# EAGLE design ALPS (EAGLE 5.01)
MFG: AVX; PN: TCJR106M006R0500
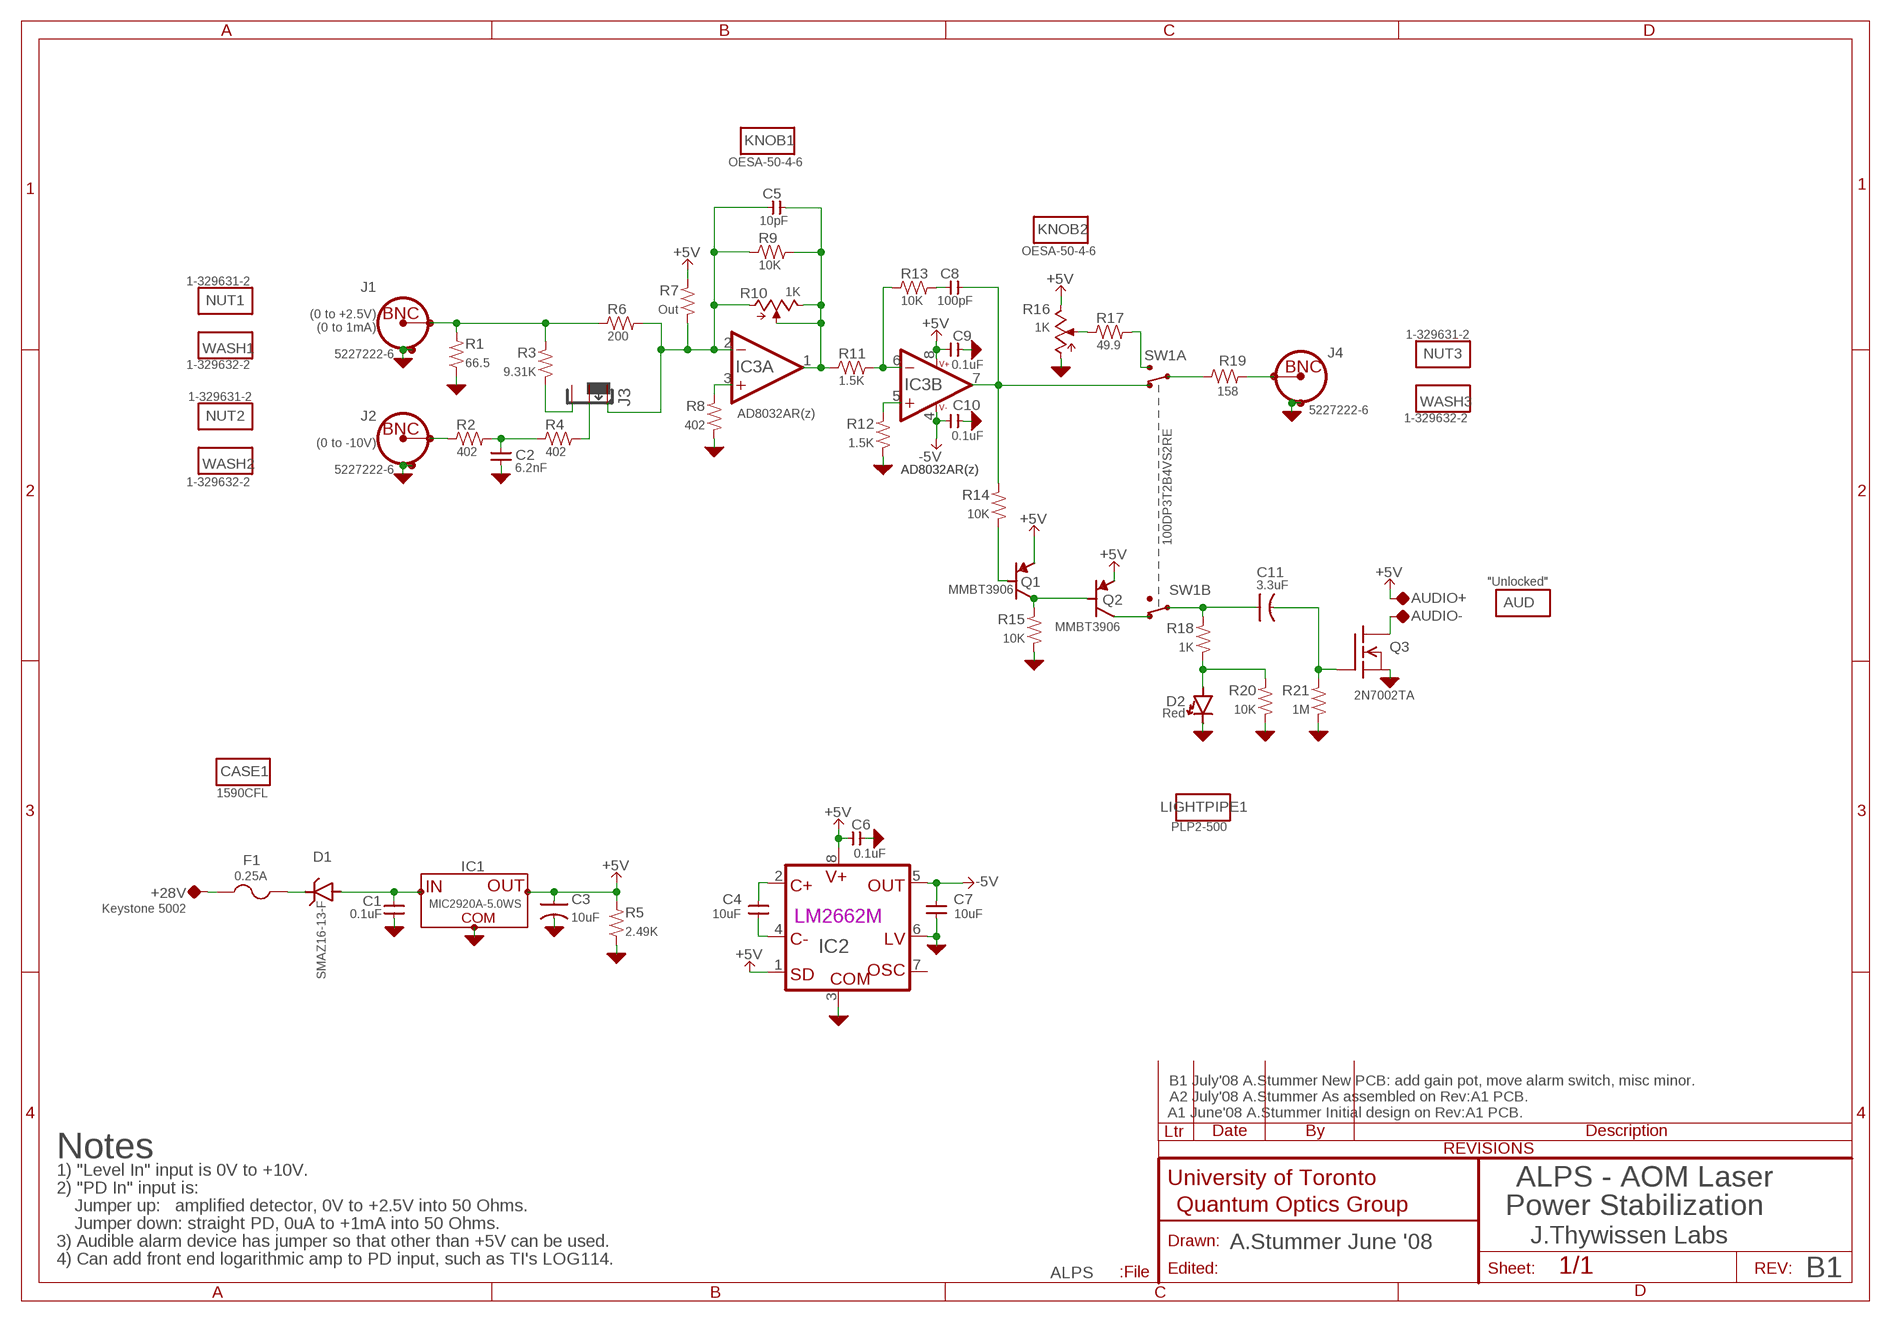
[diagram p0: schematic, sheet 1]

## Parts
+28V  Keystone 5002  TP-0.042B  [TP-0.042B]
AUD  "Unlocked"  MISC  [MISC]
AUDIO+  Keystone 5002  TP-0.042B  [TP-0.042B]
AUDIO-  Keystone 5002  TP-0.042B  [TP-0.042B]
C1  0.1uF  CAP-V-0805  [2012(0805)]
C2  6.2nF  CAP-V-0805  [2012(0805)]
C3  10uF  CAP-POL-1206  [3216(1206)]
C4  10uF  CAP-V-0805  [2012(0805)]
C5  10pF  CAP-H-0805  [2012(0805)]
C6  0.1uF  CAP-H-0805  [2012(0805)]
C7  10uF  CAP-V-0805  [2012(0805)]
C8  100pF  CAP-H-0805  [2012(0805)]
C9  0.1uF  CAP-H-0805  [2012(0805)]
C10  0.1uF  CAP-H-0805  [2012(0805)]
C11  3.3uF  CAP-POL-0805  [2012(0805)]
CASE1  1590CFL  MISC  [MISC]
D1  SMAZ16-13-F  ZENER-EIA-A  [EIA-A(SMA)]
D2  Red  LED-1209  [1209]
F1  0.25A  FUSE-5X20-4  [FUSE]
IC1  MIC2920A-5.0WS  78-SOT223  [SOT223]
IC2  LM2662M  LM2663M  [SOIC-8]
IC3  AD8032AR(z)  OPAMP_DUAL-SOIC8  [SOIC-8]
J1  5227222-6  CONN-BNC-TYPE1VERT  [CONN-BNC-AMP-TYPE1VERT]
J2  5227222-6  CONN-BNC-TYPE1VERT  [CONN-BNC-AMP-TYPE1VERT]
J3  JUMPER-1X3-3  [JUMPER-3]
J4  5227222-6  CONN-BNC-TYPE1VERT  [CONN-BNC-AMP-TYPE1VERT]
KNOB1  OESA-50-4-6  MISC  [MISC]
KNOB2  OESA-50-4-6  MISC  [MISC]
LIGHTPIPE1  PLP2-500  MISC  [MISC]
NUT1  1-329631-2  MISC  [MISC]
NUT2  1-329631-2  MISC  [MISC]
NUT3  1-329631-2  MISC  [MISC]
Q1  MMBT3906  BJT-PNP-SOT23  [SOT23]
Q2  MMBT3906  BJT-PNP-SOT23  [SOT23]
Q3  2N7002TA  MOSFET-N-SOT23  [SOT23]
R1  66.5  R-V-0805  [2012(0805)]
R2  402  R-H-0805  [2012(0805)]
R3  9.31K  R-V-0805  [2012(0805)]
R4  402  R-H-0805  [2012(0805)]
R5  2.49K  R-V-0805  [2012(0805)]
R6  200  R-H-0805  [2012(0805)]
R7  Out  R-V-0805  [2012(0805)]
R8  402  R-V-0805  [2012(0805)]
R9  10K  R-H-0805  [2012(0805)]
R10  1K  POT-PRECISION_SPR_RV8  [PRECISION-SPR-RV8(POT)]
R11  1.5K  R-H-0805  [2012(0805)]
R12  1.5K  R-V-0805  [2012(0805)]
R13  10K  R-H-0805  [2012(0805)]
R14  10K  R-V-0805  [2012(0805)]
R15  10K  R-V-0805  [2012(0805)]
R16  1K  POT-PRECISION_SPR_RV8  [PRECISION-SPR-RV8(POT)]
R17  49.9  R-H-0805  [2012(0805)]
R18  1K  R-V-0805  [2012(0805)]
R19  158  R-H-0805  [2012(0805)]
R20  10K  R-V-0805  [2012(0805)]
R21  1M  R-V-0805  [2012(0805)]
SW1  100DP3T2B4VS2RE  SWITCH_DPDT-ESWITCH_100DP?VS2  [SWITCH-ESWITCH_100DP?VS2]
WASH1  1-329632-2  MISC  [MISC]
WASH2  1-329632-2  MISC  [MISC]
WASH3  1-329632-2  MISC  [MISC]

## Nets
+5V: AUDIO+.TP C3.2(POS) C6.1 C9.1 IC1.3(OUT) IC2.1(SD) IC2.8(V+) IC3.8(.:V+) Q1.2(E) Q2.2(E) R5.2 R7.2 R16.CW
-5V: C7.2 C10.1 IC2.5(OUT) IC3.4(.:V-)
AGND: C1.1 C2.1 C3.1(NEG) C6.2 C7.1 C9.2 C10.2 D2.K(C) IC1.2@1(COM) IC2.3(COM) IC2.6(LV) J1.SHIELD1 J1.SHIELD2 J2.SHIELD1 J2.SHIELD2 J4.SHIELD1 J4.SHIELD2 Q3.2(S) R1.1 R5.1 R8.1 R12.1 R15.1 R16.CCW R20.1 R21.1
N$1: J4.CONDUCTOR R19.2
N$2: C8.2 IC3.7(B:OUT) R14.2 SW1.NC1(A:NC1)
N$3: IC3.6(B:-IN) R11.2 R13.1
N$4: C8.1 R13.2
N$5: R19.1 SW1.C1(A:COM1)
N$6: R17.2 SW1.NO1(A:NO1)
N$7: J2.CONDUCTOR R2.1
N$8: IC3.5(B:+IN) R12.2
N$9: Q1.3(C) Q2.1(B) R15.2
N$10: J1.CONDUCTOR R1.2 R3.2 R6.1
N$11: Q1.1(B) R14.1
N$12: C11.2(POS) R18.2 SW1.C2(B:COM1)
N$13: D2.A R18.1 R20.2
N$14: Q2.3(C) SW1.NC2(B:NC1)
N$15: C11.1(NEG) Q3.1(G) R21.2
N$16: AUDIO-.TP Q3.3(D)
N$17: C1.2 D1.1A(A) IC1.1(VI)
N$18: C4.2 IC2.2(C+)
N$19: +28V.TP F1.1A
N$20: D1.2K(C) F1.2A
N$21: C5.2 IC3.1(A:OUT) R9.2 R10.CW R10.W R11.1
N$22: C5.1 IC3.2(A:-IN) J3.1 R6.2 R7.1 R9.1 R10.CCW
N$23: J3.2 R4.2
N$24: R16.W R17.1
N$25: IC3.3(A:+IN) R8.2
N$26: C4.1 IC2.4(C-)
N$27: C2.2 R2.2 R4.1
N$29: J3.3 R3.1
Unconnected: IC2.7(OSC) SW1.NO2(B:NO1)

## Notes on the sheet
- (0 to +2.5V)
- (0 to 1mA)
- (0 to -10V)
- B1 July'08 A.Stummer New PCB: add gain pot, move alarm switch, misc minor.
- A2 July'08 A.Stummer As assembled on Rev:A1 PCB.
- A1 June'08 A.Stummer Initial design on Rev:A1 PCB.
- Notes
- 1) "Level In" input is 0V to +10V.
- ALPS - AOM Laser
- 2) "PD In" input is:
- Jumper up:   amplified detector, 0V to +2.5V into 50 Ohms. | Power Stabilization
- Jumper down: straight PD, 0uA to +1mA into 50 Ohms.
- 3) Audible alarm device has jumper so that other than +5V can be used. | A.Stummer June '08 | J.Thywissen Labs
- 4) Can add front end logarithmic amp to PD input, such as TI's LOG114.
- B1

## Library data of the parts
+28V AUDIO+ AUDIO- = QuantumOptics:TP: Testpoint, test point on schematic, on PCB either SMT pad, small hole or loop style TP.
AUD CASE1 KNOB1 KNOB2 LIGHTPIPE1 NUT1-NUT3 WASH1-WASH3 = QuantumOptics:MISC: Miscellaneous Part, just a placeholder for miscellaeous parts
C1 C2 C4 C7 = QuantumOptics:CAP-V-: Cap, SMT and Through-hole, 0402 and up.
C3 C11 = QuantumOptics:CAP-POL-: Capacitor, Polarized, SMT 0805 and up, probably tantalum.
C5 C6 C8-C10 = QuantumOptics:CAP-H-: Cap, SMT and Through-hole, 0402 and up.
D1 = QuantumOptics:ZENER: Zener
D2 = QuantumOptics:LED: LED
F1 = QuantumOptics:FUSE: Fuse
IC1 = QuantumOptics:78*: Positive regulator, probably fixed output. E.g. SOT-223 Micrel MIC2920, http://www.micrel.com/_PDF/mic2920.pdf e.g. uA78L05ACPK, http://www-s.ti.com/sc/ds/ua78l05a.pdf
IC2 = QuantumOptics:LM2663: LM2663, switched cap DC-DC converter. Inverter, doubler, supply splitter.
IC3 = QuantumOptics:OPAMP_DUAL: Dual Op Amp, common pinouts. Based on http://www.analog.com/static/imported-files/data_sheets/AD8651_8652.pdf
J1 J2 J4 = QuantumOptics:CONN-BNC: BNC PCB, horizontal or vertical, e.g. vertical: Amp 227677-1, nut 1-329631-2, shoulder washer 330620. The two shield connections allow the assembly on either side of the board. Horiz isolated: 5227222-6, http://catalog.tycoelectronics.com/TE/bin/TE.Connect?C=1&M=BYPN&TCPN=5227222-6&RQPN=5227222-6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; DESC: Input?
J3 = QuantumOptics:JUMPER-1X3: Jumper, header, SIP on 0.1" grid, for option selection.
Q1 Q2 = QuantumOptics:BJT-PNP: PNP BJT, generic, p/n defined by VALUE field. E.g. Fairchild MMBT3906 (abs max 40V, 200mA. hFE>80@10mA.
Q3 = QuantumOptics:MOSFET-N: Mosfet, N-Channel, generic enhancement mode N-FET.
R1 R3 R5 R7 R8 R12 R14 R15 R18 R20 R21 = QuantumOptics:R-V-*: Resistor, SMT & Through-Hole, vertical symbol
R2 R4 R6 R9 R11 R13 R17 R19 = QuantumOptics:R-H-*: Resistor, SMT & Through-Hole, horizontal symbol
R10 R16 = QuantumOptics:POT: Pot, regular or trimpot
SW1 = QuantumOptics:SWITCH_DPDT: Switch, DPDT

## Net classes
0 default: width 0.203 mm, clearance 0.203 mm

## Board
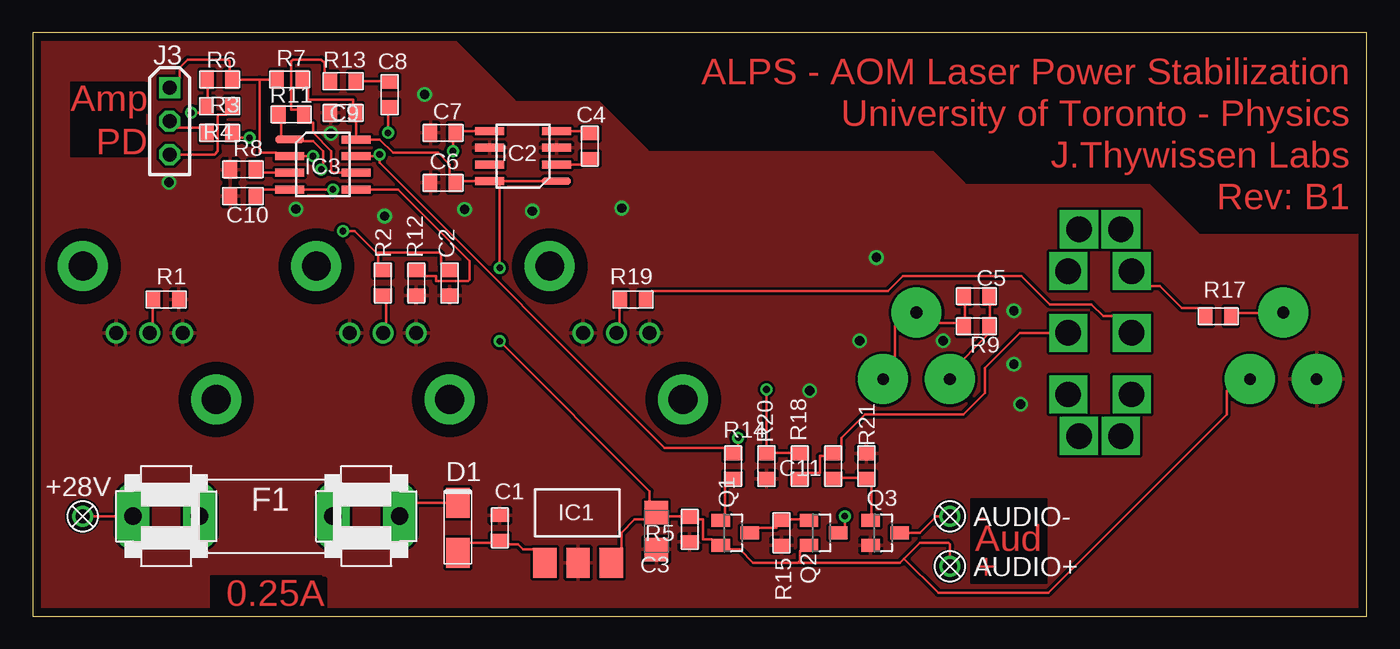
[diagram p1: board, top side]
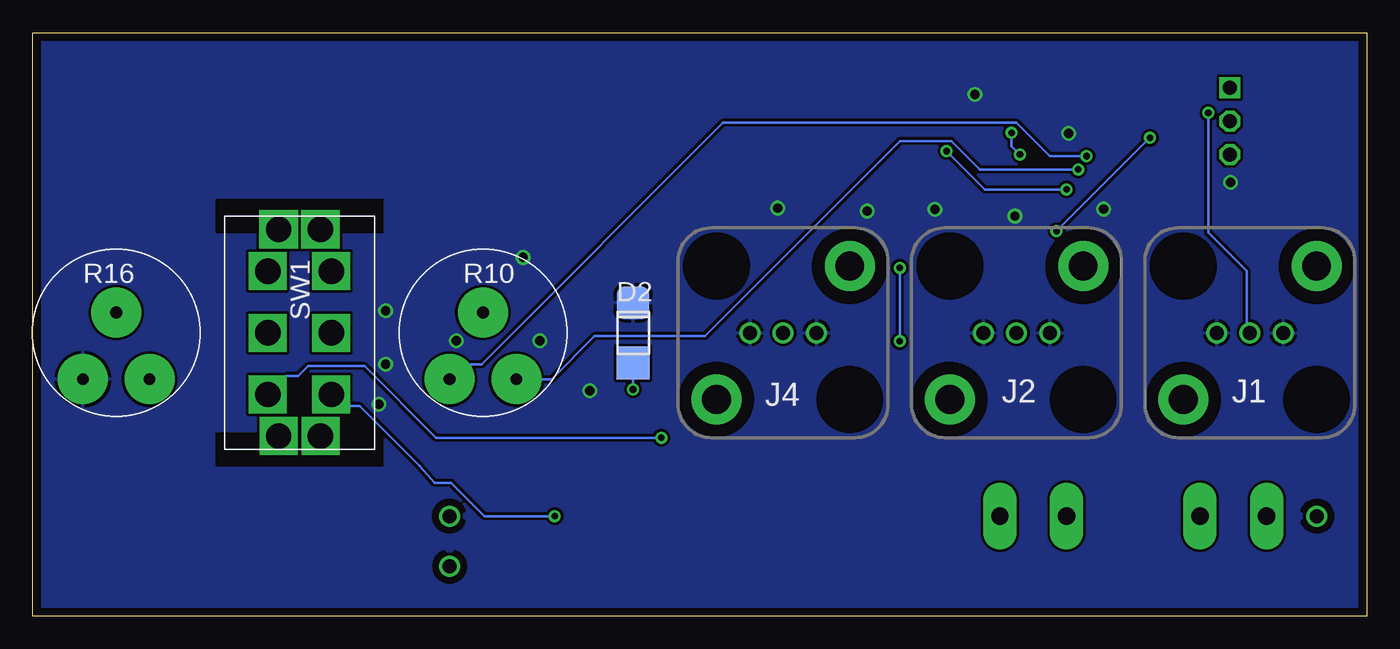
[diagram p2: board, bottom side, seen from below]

Size 101.6 x 44.45 mm. Coordinates in mm from the lower left corner, seen from the top.
Outline: 0,0 101.6,0 101.6,44.45 0,44.45 0,0
Copper layers (1*16): Top 0.035mm / dielectric 1.5mm / Bottom 0.035mm
Design rules "DRC standard check (8mil trace and gap, 20mil drill, etc)": minimum track width 7mil, minimum drill 20mil, track to track 7mil, track to pad 7mil, pad to pad 7mil, via to via 7mil, smd to smd 7mil, copper to edge 25mil, drill to drill 8mil, minimum pad ring 10mil, minimum via ring 8mil, stop-mask expansion 4mil, vias tented up to drill 0mil, thermal gap 10mil
tRestrict: 19 lines

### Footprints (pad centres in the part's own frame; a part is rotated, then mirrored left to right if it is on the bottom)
TP-0.042B = drill 1.067 round: TP 0,0
2012(0805) = smd 1.016 x 1.397: 1 -0.953,0; 2 0.953,0
3216(1206) = smd 1.8 x 1.8: 1 -1.4,0; 2 1.4,0
EIA-A(SMA) = smd 2.3 x 1.8: 1A -1.905,0; 2K 1.905,0
1209 = smd 2.5 x 2.5: A 2.3,0; K -2.3,0
FUSE = drill 1.321 pad 2.54 long: 1A -10.16,0; 1B -5.08,0; 2A 10.16,0; 2B 5.08,0
SOT223 = smd 1.778 x 2.286: 1 -2.54,-2.54; 2@1 0,-2.54; 3 2.54,-2.54
SOIC-8 = smd 0.6 x 2.2: 1 -1.27,-2.54; 2 0,-2.54; 3 1.27,-2.54; 4 2.54,-2.54; 5 2.54,2.54; 6 1.27,2.54; 7 0,2.54; 8 -1.27,2.54
CONN-BNC-AMP-TYPE1VERT = drill 1.067 round: CONDUCTOR 0,0; SHIELD1 -2.54,0; SHIELD2 2.54,0 | drill 2.184 pad 3.81 round: MTG1 -5.08,-5.08; MTG2 5.08,5.08
JUMPER-3 = drill 1.067 square: 1 0,2.54 | drill 1.067 octagon: 2 0,0; 3 0,-2.54
SOT23 = smd 1 x 1.4: 1 -0.953,-0.953; 2 0.953,-0.953; 3 0,1.27
PRECISION-SPR-RV8(POT) = drill 0.889 pad 3.81 round: CCW -2.54,-3.531; CW 2.54,-3.531; W 0,1.549
SWITCH-ESWITCH_100DP?VS2 = drill 1.93 square: C1 -2.42,0; C2 2.42,0; MTG3 1.595,-7.875; MTG4 -1.595,-7.875; NC1 -2.42,-4.7; NC2 2.42,-4.7; NO1 -2.42,4.7; NO2 2.42,4.7 | drill 1.93 pad 2.946 square: MTG1 -1.595,7.875; MTG2 1.595,7.875

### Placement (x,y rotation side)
+28V  3.81,7.62 180 top
AUD  not placed on the board
AUDIO+  69.85,3.81 270 top
AUDIO-  69.85,7.62 0 top
C1  35.56,6.73 270 top
C2  31.75,25.4 90 top
C3  47.5,6.48 90 top
C4  42.42,35.81 270 top
C5  71.88,24.38 180 top
C6  31.24,33.02 180 top
C7  31.24,36.83 0 top
C8  27.18,39.75 270 top
C9  23.62,38.35 180 top
C10  16,32 180 top
C11  60.96,11.43 90 top
CASE1  not placed on the board
D1  32.38,6.73 90 top
D2  55.88,21.59 270 bottom
F1  17.78,7.62 0 top
IC1  41.53,6.6 0 top
IC2  37.34,34.42 90 top
IC3  22.1,35.05 270 top
J1  8.89,21.59 0 bottom
J2  26.67,21.59 0 bottom
J3  10.41,37.72 0 top
J4  44.45,21.59 0 bottom
KNOB1  not placed on the board
KNOB2  not placed on the board
LIGHTPIPE1  not placed on the board
NUT1  not placed on the board
NUT2  not placed on the board
NUT3  not placed on the board
Q1  53.34,6.35 270 top
Q2  60.07,6.35 270 top
Q3  64.77,6.35 270 top
R1  10.16,24.13 180 top
R2  26.67,25.4 90 top
R3  14.22,38.86 180 top
R4  14.22,36.83 180 top
R5  50.04,6.6 90 top
R6  14.22,40.89 0 top
R7  19.56,40.89 0 top
R8  16,34.04 0 top
R9  71.88,22.1 180 top
R10  67.31,21.59 0 bottom
R11  19.68,38.23 0 top
R12  29.21,25.4 90 top
R13  23.62,40.77 0 top
R14  53.34,11.43 90 top
R15  57.02,6.35 90 top
R16  95.25,21.59 0 bottom
R17  90.3,22.86 180 top
R18  58.42,11.43 270 top
R19  45.72,24.13 180 top
R20  55.88,11.43 90 top
R21  63.5,11.43 270 top
SW1  81.28,21.59 0 bottom
U$18  [TITLEBLOCK_PCB]  not placed on the board
WASH1  not placed on the board
WASH2  not placed on the board
WASH3  not placed on the board

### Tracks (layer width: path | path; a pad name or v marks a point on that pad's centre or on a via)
+5V  (via drill 0.51)
  Top 0.203: IC2.8 32.64,33.15 C6.1 31.75,33.66 31.75,34.42 30.86,35.31 27.43,35.31 26.42,36.32 IC3.8 24.64,37.72 C9.1 24.38,38.99 24.38,39.37 20.95,39.37 20.95,40.26 R7.2 | IC2.8 IC2.1 | C3.2 48.39,7.62 49.4,7.62 R5.2 50.67,7.37 51.05,7.37 51.05,5.84 51.69,5.84 Q1.2 53.09,5.08 53.85,5.08 54.86,4.06 58.29,4.06 58.36,4.13 | 58.36,4.13 58.42,4.19 58.42,4.95 Q2.2 | IC1.3 44.83,5.08 44.83,6.35 45.85,7.37 46.61,7.37 C3.2 | 66.36,4.38 66.04,4.06 58.42,4.06 58.36,4.13 | 66.36,4.38 67.56,5.59 69.72,5.59 69.85,5.46 AUDIO+.TP | R16.CW 90.93,17.14 90.93,15.37 77.34,1.78 68.96,1.78 66.36,4.38 | v35.56,26.54 35.56,32.89 IC2.8 | v35.56,20.95 46.99,9.53 46.99,8.76 C3.2
  Bottom 0.203: v35.56,20.95 v35.56,26.54
-5V  (via drill 0.51)
  Top 0.203: C10.1 17.4,32.51 IC3.4 v22.86,32.51 | IC2.5 32.64,36.96 C7.2 32,36.2 v32,35.43
  Bottom 0.203: v22.86,32.51 29.08,32.51 v32,35.43
AGND  (via drill 0.71)
  other vias: 29.84,39.75 32.89,30.99 26.8,30.48 22.71,36.78 20.04,31.01 10.36,33.05 38.05,30.86 44.86,31.09 69.34,20.98 74.73,23.27 74.73,19.2 75.23,16.15 62.99,20.98 59.18,17.17 64.26,27.33
  pour Top: 0,0 101.6,0 101.6,29.21 88.9,29.21 85.09,33.02 71.12,33.02 68.58,35.56 46.99,35.56 43.18,39.37 36.83,39.37 31.75,44.45 0,44.45
  pour Bottom: 0,0 101.6,0 101.6,44.45 0,44.45
N$1
  Top 0.203: R19.2 44.7,23.5 44.7,22.35 J4.CONDUCTOR
N$2  (via drill 0.51)
  Top 0.203: 26.42,35.05 26.42,34.54 48.13,12.83 52.7,12.83 R14.2 53.72,12.83 v53.72,13.59 | IC3.7 26.42,35.05 | v27.05,36.83 27.05,38.35 C8.2 | 26.42,35.05 v26.42,35.18
  Bottom 0.203: v27.05,36.83 27.05,35.81 v26.42,35.18 | v53.72,13.59 70.87,13.59 76.33,19.05 80.64,19.05 81.41,18.29 82.3,18.29 SW1.NC1
N$3
  Top 0.203: IC3.6 22.86,33.78 22.73,33.91 22.73,35.43 21.34,36.83 21.34,37.59 21.08,37.59 R11.2 20.19,38.61 19.68,38.61 19.68,42.29 19.81,42.42 21.97,42.42 22.23,42.16 22.23,41.4 R13.1
N$4
  Top 0.203: R13.2 26.54,40.77 C8.1
N$5
  Top 0.203: R19.1 47.12,24.77 65.15,24.77 66.29,25.91 75.31,25.91 77.47,23.75 80.64,23.75 81.53,22.86 82.3,22.86 SW1.C1
N$6
  Top 0.203: R17.2 88.9,23.5 87.5,23.5 85.85,25.15 85.09,25.15 SW1.NO1
N$7
  Top 0.203: R2.1 26.92,24 26.92,22.35 J2.CONDUCTOR
N$8
  Top 0.203: R12.2 29.84,25.91 30.73,25.91 30.73,25.53 33.15,25.53 33.27,25.65 33.27,27.05 27.81,32.51 IC3.5
N$9
  Top 0.203: Q2.1 58.42,7.37 57.66,7.37 R15.2 56.64,6.86 56.64,6.73 55.24,6.73 Q1.3
N$10  (via drill 0.51)
  Top 0.203: R6.1 13.34,40.26 13.34,39.5 R3.2 12.83,38.35 v12.06,38.35 | R1.2 9.14,23.5 9.14,22.35 J1.CONDUCTOR
  Bottom 0.203: v12.06,38.35 12.06,29.21 9.14,26.29 9.14,22.35 J1.CONDUCTOR
N$11
  Top 0.203: R14.1 52.7,10.03 52.7,7.75 Q1.1
N$12
  Top 0.203: R18.2 59.05,10.92 59.94,10.92 59.94,12.19 60.33,12.19 C11.2 61.59,12.83 61.59,13.59 63.37,15.37 70.87,15.37 72.52,17.02 72.52,18.92 75.18,21.59 SW1.C2
N$13  (via drill 0.51)
  Top 0.203: R18.1 57.78,12.45 56.52,12.45 R20.2 v55.88,17.27
  Bottom 0.203: v55.88,17.27 D2.A
N$14  (via drill 0.51)
  Top 0.203: v61.85,7.62 61.85,6.73 Q2.3
  Bottom 0.203: v61.85,7.62 67.18,7.62 69.72,10.16 70.99,10.16 72.14,11.43 76.71,16 77.98,16 78.99,17.02 SW1.NC2
N$15
  Top 0.203: C11.1 61.59,10.54 62.87,10.54 R21.2 63.88,10.03 63.88,7.75 Q3.1
N$16
  Top 0.203: AUDIO-.TP 68.83,7.62 67.56,6.35 Q3.3 65.91,6.35
N$17
  Top 0.203: D1.1A 33.27,5.59 34.92,5.59 C1.2 36.2,5.46 36.96,5.46 37.34,5.08 38.23,5.08 IC1.1
N$18
  Top 0.203: C4.2 41.78,34.42 IC2.2
N$19
  Top 0.203: +28V.TP F1.1A
N$20
  Top 0.203: D1.2K 29.08,8.64 F1.2A
N$21  (via drill 0.51)
  Top 0.203: C5.2 70.99,23.75 70.99,22.73 R9.2 70.48,22.35 69.09,22.35 R10.W 65.66,22.1 65.66,19.81 R10.CW | R11.1 18.92,37.59 18.92,36.58 IC3.1 20.57,36.2 21.34,36.2 22.1,35.43 22.1,34.16 v21.97,34.04
  Bottom 0.203: v21.97,34.04 29.46,34.04 31.62,36.2 35.56,36.2 50.42,21.34 58.8,21.34 62.1,18.03 62.99,18.03 R10.CW
N$22  (via drill 0.51)
  Top 0.203: 17.27,40.89 R6.2 14.99,41.53 14.99,42.29 14.86,42.42 11.81,42.42 11.18,41.78 11.18,41.02 J3.1 | 17.27,40.89 R7.1 | 17.27,40.89 17.27,35.31 18.54,35.31 IC3.2 v21.34,35.05 | C5.1 72.9,23.75 72.9,22.73 R9.1 72.83,21.53 69.85,18.54 R10.CCW
  Bottom 0.203: v21.34,35.05 24.13,35.05 26.67,37.59 49.02,37.59 67.44,19.18 68.33,19.18 R10.CCW
N$23
  Top 0.203: R4.2 12.83,37.21 10.92,37.21 J3.2
N$24
  Top 0.203: R17.1 91.69,23.11 93.47,23.11 R16.W
N$25
  Top 0.203: R8.2 17.4,33.78 IC3.3
N$26
  Top 0.203: C4.1 41.78,36.96 IC2.4
N$27  (via drill 0.51)
  Top 0.203: v16.51,36.45 15.62,36.45 R4.1 | v23.62,29.34 24.51,29.34 26.23,27.62 | 26.23,27.62 26.29,27.56 26.29,26.8 R2.2 | C2.2 31.11,26.8 31.11,27.56 30.99,27.69 26.29,27.69 26.23,27.62
  Bottom 0.203: v16.51,36.45 v23.62,29.34
N$29
  Top 0.203: R3.1 14.73,38.23 14.1,38.23 14.1,35.43 13.84,35.18 J3.3

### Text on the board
Top: ALPS - AOM Laser Power Stabilization | Amp | University of Toronto - Physics | PD | J.Thywissen Labs | Rev: B1 | - | Aud | 0.25A | +
Document: A. Stummer July'08 | B1 | 0.2mm(0.008") | 0.2mm(0.008") | 0.2mm(0.008") | 0.125mm(0.005") | 0.125mm(0.005") | Following are misc parts: | B1 July'08 A.Stummer Redesign. | A2 July'08 A.Stummer As assembled on Rev:A1 PCB. | A1 June'08 A.Stummer Initial design on Rev:A1 PCB.
Text: ALPS - AOM Laser | Power Stabilization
